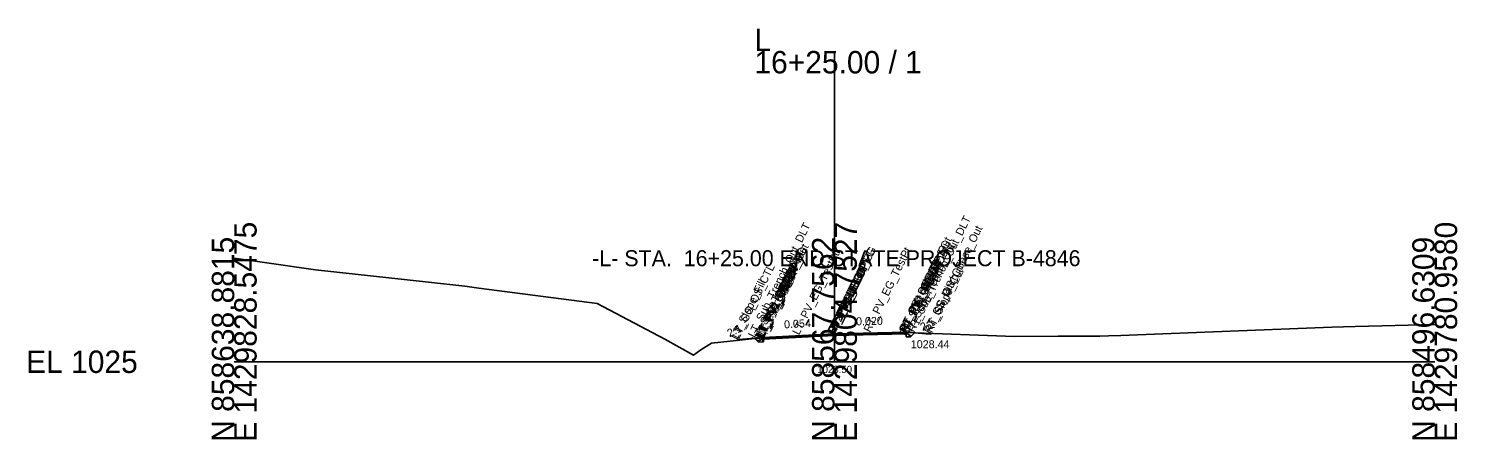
# Model space of a CAD drawing. Extents: x -26 to 153, y -10 to 13058.
# Drawn here: x -25.7 to 152.8, y 9490.3 to 9541.6 of the extents above; entities that cross this region are included whole.
import ezdxf

# ---------------------------------------------------------------- set-up
doc = ezdxf.new("R2010")
doc.units = 0
for name, color, linetype in [('Default', 7, 'Continuous'), ('Exist Cross Section Cell', 7, 'Continuous'), ('Exist XS Ground Line', 7, 'Continuous'), ('Prop CMT Pvmt Course 1', 7, 'Continuous'), ('Prop CMT Pvmt Course 2', 7, 'Continuous'), ('Prop CMT Pvmt Surface', 7, 'Continuous'), ('Prop CMT Pvmt Surface Shoulder', 7, 'Continuous'), ('Prop CMT Pvmt Wedge Surface 1', 7, 'Continuous'), ('Prop CMT Pvmt Wedge Surface 2', 7, 'Continuous'), ('Prop CMT Shld Paved Course 1', 7, 'Continuous'), ('Prop CMT Shld Paved Course 2', 7, 'Continuous'), ('Prop CMT Slope Grass', 7, 'Continuous'), ('Prop CMT Subgrade Daylight Point', 7, 'Continuous'), ('Prop CMT Subgrade Earthwork', 7, 'Continuous'), ('Prop XS Ditch Standard Text', 7, 'Continuous'), ('Prop XS Dump Level', 7, 'Continuous'), ('Prop XS SE Text', 7, 'Continuous'), ('Prop XS Side Slope Text', 7, 'Continuous'), ('Prop XSC Text', 7, 'Continuous')]:
    doc.layers.add(name, color=color, linetype=linetype)

msp = doc.modelspace()

# ---------------------------------------------------------------- linework, layer by layer
at = {"layer": 'Exist Cross Section Cell'}
for p, q in [((75, 9500), (75, 9538.8)), ((0, 9500), (75, 9500)), ((75, 9500), (150, 9500))]:
    msp.add_line(p, q, dxfattribs=at)
at = {"layer": 'Exist XS Ground Line'}
msp.add_lwpolyline([(0, 9512.93), (4.35, 9512.29), (10.14, 9511.47), (24.29, 9509.92), (28.8, 9509.45), (30.55, 9509.21), (45.36, 9507.29), (53.8, 9502.82), (57.37, 9500.84), (58.29, 9501.48), (59.65, 9502.32), (65.47, 9502.95), (66.08, 9503.02), (66.51, 9503.04), (74.92, 9503.49), (79.94, 9503.59), (84.01, 9503.67), (97.48, 9503.15), (102.94, 9503.18), (108.14, 9503.2), (109.24, 9503.22), (110.78, 9503.29), (124.43, 9503.83), (137.15, 9504.31), (140.05, 9504.4), (150, 9504.65)], dxfattribs=at)
at = {"layer": 'Prop CMT Pvmt Course 1'}
for points in [[(75, 9503.5), (66.05, 9503.01)], [(66.14, 9502.89), (75, 9503.37)], [(75, 9503.5), (83.95, 9503.68)], [(83.95, 9503.55), (75, 9503.37)], [(75, 9503.29), (75, 9503.5)], [(75, 9503.29), (75, 9503.5)], [(75, 9503.37), (75, 9503.29), (75, 9503.29)], [(75, 9503.37), (75, 9503.29), (75, 9503.29)], [(83.95, 9503.68), (83.95, 9503.47), (83.95, 9503.47), (83.95, 9503.55)], [(66.05, 9503.01), (66.05, 9502.81)], [(66.05, 9502.81), (66.14, 9502.81)], [(66.14, 9502.81), (66.14, 9502.89)]]:
    msp.add_lwpolyline(points, dxfattribs=at)
at = {"layer": 'Prop CMT Pvmt Course 2'}
for points in [[(83.95, 9503.13), (83.95, 9503.13), (83.95, 9503.47), (83.95, 9503.47)], [(83.95, 9503.47), (83.95, 9503.13)], [(66.14, 9502.81), (66.05, 9502.81)], [(66.05, 9502.81), (66.05, 9502.47)], [(66.05, 9502.47), (66.14, 9502.48)], [(66.14, 9502.48), (66.14, 9502.81)]]:
    msp.add_lwpolyline(points, dxfattribs=at)
at = {"layer": 'Prop CMT Pvmt Surface'}
for points in [[(75, 9503.5), (66.05, 9503.01)], [(75, 9503.5), (83.95, 9503.68)]]:
    msp.add_lwpolyline(points, dxfattribs=at)
at = {"layer": 'Prop CMT Pvmt Surface Shoulder'}
for points in [[(83.95, 9503.68), (83.95, 9503.68)], [(66.05, 9503.01), (66.05, 9503.01)]]:
    msp.add_lwpolyline(points, dxfattribs=at)
at = {"layer": 'Prop CMT Pvmt Wedge Surface 1'}
for points in [[(75, 9503.37), (66.14, 9502.89)], [(75, 9503.37), (83.95, 9503.55)], [(83.95, 9503.47), (83.95, 9503.68)], [(83.95, 9503.55), (83.95, 9503.47), (83.95, 9503.47)], [(66.05, 9502.81), (66.05, 9503.01)], [(66.14, 9502.81), (66.05, 9502.81)], [(66.14, 9502.89), (66.14, 9502.81)]]:
    msp.add_lwpolyline(points, dxfattribs=at)
at = {"layer": 'Prop CMT Pvmt Wedge Surface 2'}
for points in [[(75, 9503.29), (83.95, 9503.47)], [(83.95, 9503.47), (83.95, 9503.68)], [(75, 9503.29), (66.05, 9502.81)], [(66.05, 9502.81), (66.05, 9503.01)]]:
    msp.add_lwpolyline(points, dxfattribs=at)
at = {"layer": 'Prop CMT Shld Paved Course 1'}
for points in [[(83.95, 9503.68), (83.95, 9503.68)], [(83.95, 9503.68), (84.16, 9503.46)], [(83.95, 9503.47), (83.95, 9503.68)], [(84.16, 9503.46), (83.95, 9503.47)], [(66.05, 9503.01), (65.84, 9502.8)], [(65.84, 9502.8), (66.05, 9502.81)], [(66.05, 9503.01), (66.05, 9503.01)], [(66.05, 9502.81), (66.05, 9503.01)]]:
    msp.add_lwpolyline(points, dxfattribs=at)
at = {"layer": 'Prop CMT Shld Paved Course 2'}
for points in [[(83.95, 9503.47), (84.16, 9503.46)], [(83.95, 9503.13), (83.95, 9503.47)], [(84.16, 9503.46), (84.16, 9503.46)], [(84.16, 9503.46), (84.5, 9503.12)], [(65.84, 9502.8), (65.5, 9502.46)], [(65.5, 9502.46), (66.05, 9502.47)], [(66.05, 9502.81), (65.84, 9502.8)], [(65.84, 9502.8), (65.84, 9502.8)], [(66.05, 9502.47), (66.05, 9502.81)], [(84.5, 9503.12), (83.95, 9503.13)]]:
    msp.add_lwpolyline(points, dxfattribs=at)
at = {"layer": 'Prop CMT Slope Grass'}
for points in [[(83.95, 9503.68), (86.95, 9503.44)], [(86.95, 9503.44), (87.18, 9503.55)], [(86.95, 9503.44), (86.95, 9503.44)], [(66.05, 9503.01), (63.05, 9502.77), (62.84, 9502.67)]]:
    msp.add_lwpolyline(points, dxfattribs=at)
at = {"layer": 'Prop CMT Subgrade Earthwork'}
for points in [[(83.95, 9503.13), (83.93, 9503.67)], [(84.5, 9503.12), (84.97, 9503.59)], [(65.5, 9502.46), (65.03, 9502.93)], [(66.05, 9502.47), (65.5, 9502.46)], [(66.14, 9502.48), (66.05, 9502.47)], [(66.14, 9502.48), (66.16, 9503.02)], [(83.95, 9503.13), (83.95, 9503.13)], [(83.95, 9503.13), (84.5, 9503.12)]]:
    msp.add_lwpolyline(points, dxfattribs=at)

# ---------------------------------------------------------------- texts
at = {"layer": 'Default'}
msp.add_text('-', height=0.0001, dxfattribs=at).set_placement((0, 9500))
at = {"layer": 'Exist Cross Section Cell'}
for s, p in [('L', (65, 9538.8)), ('16+25.00 / 1', (65, 9536)), ('EL 1025', (-26, 9498.6))]:
    msp.add_text(s, height=2.8, dxfattribs=at).set_placement(p)
for s, p in [('E 1429828.5475', (2.8, 9490)), ('E 1429804.7527', (77.8, 9490)), ('E 1429780.9580', (152.8, 9490)), ('N 858638.8815', (0, 9490)), ('N 858567.7562', (75, 9490)), ('N 858496.6309', (150, 9490))]:
    msp.add_text(s, height=2.8, rotation=90, dxfattribs=at).set_placement(p)
at = {"layer": 'Prop CMT Subgrade Daylight Point'}
msp.add_text('1028.50', height=0.9, dxfattribs=at).set_placement((72.85, 9498.6))
at = {"layer": 'Prop XS Ditch Standard Text'}
msp.add_text('1028.44', height=1, dxfattribs=at).set_placement((84.54, 9501.69))
at = {"layer": 'Prop XS Dump Level'}
for s, p in [('RT_Sub_Trench_Out_DLT', (84.97, 9503.59)), ('LT_Sub_Trench_Out_DLT', (65.03, 9502.93)), ('RT_SS_Ditch_Base_Out', (86.95, 9503.44)), ('LT_PV_OEEOP_EG', (66.14, 9503.02)), ('LT_PV_Sub_Tie_Out', (66.16, 9503.02)), ('RT_PV_IEEOP_EG', (75, 9503.5)), ('LT_PV_IEEOP_EG', (75, 9503.5)), ('RT_PV_EG_TestPt', (79.47, 9503.59)), ('RT_PV_Sub_Tie_Out', (83.93, 9503.67)), ('RT_PV_OEEOP_EG', (83.95, 9503.67)), ('RT_PS2_Shelf_Out', (84.16, 9503.46)), ('RT_Sub_Trench_Out', (84.5, 9503.12)), ('LT_Sub_Trench_Out', (65.5, 9502.46)), ('LT_PS2_Shelf_Out', (65.84, 9502.8)), ('LT_PV1_OEEOP', (66.14, 9502.89)), ('LT_PV2_OEEOP', (66.14, 9502.81)), ('LT_PV_EG_TestPt', (70.57, 9503.26)), ('RT_PV1_IEEOP', (75, 9503.37)), ('RT_PV2_IEEOP', (75, 9503.29)), ('LT_PV1_IEEOP', (75, 9503.37)), ('LT_PV2_IEEOP', (75, 9503.29)), ('RT_PV1_OEEOP', (83.95, 9503.55)), ('RT_PV2_OEEOP', (83.95, 9503.47)), ('RT_Sub_OEEOP', (83.95, 9503.13)), ('RT_PV1_OEOT', (83.95, 9503.68)), ('RT_PS1_OEOP', (83.95, 9503.68)), ('RT_PV2_OEOT', (83.95, 9503.47)), ('RT_PS2_OEOP', (84.16, 9503.46)), ('RT_GS_OS_CTL', (86.95, 9503.44)), ('LT_GS_OS_CTL', (63.05, 9502.77)), ('LT_PS2_OEOP', (65.84, 9502.8)), ('LT_PV1_OEOT', (66.05, 9503.01)), ('LT_PS1_OEOP', (66.05, 9503.01)), ('LT_PV2_OEOT', (66.05, 9502.81)), ('LT_Sub_OEOT', (66.05, 9502.47)), ('LT_Sub_OEEOP', (66.14, 9502.48)), ('RT_Sub_OEOT', (83.95, 9503.13)), ('RT_Slope_Cut', (87.18, 9503.55)), ('LT_Slope_Fill', (62.84, 9502.67)), ('PV1_PGL', (75, 9503.5)), ('PV2_PGL', (75, 9503.29))]:
    msp.add_text(s, height=1, rotation=63.5833, dxfattribs=at).set_placement(p)
at = {"layer": 'Prop XS SE Text'}
for s, rotation, p in [('0.054', 3.091, (68.73, 9504.16)), ('0.020', 1.1458, (77.71, 9504.55))]:
    msp.add_text(s, height=1, rotation=rotation, dxfattribs=at).set_placement(p)
at = {"layer": 'Prop XS Side Slope Text'}
for p in [(86.02, 9503.81), (61.9, 9503.04)]:
    msp.add_text('2:1', height=1, rotation=26.5651, dxfattribs=at).set_placement(p)
at = {"layer": 'Prop XSC Text'}
msp.add_text('-L- STA.  16+25.00 END STATE PROJECT B-4846', height=2, dxfattribs=at).set_placement((44.73, 9511.93))

doc.saveas('drawing.dxf')
